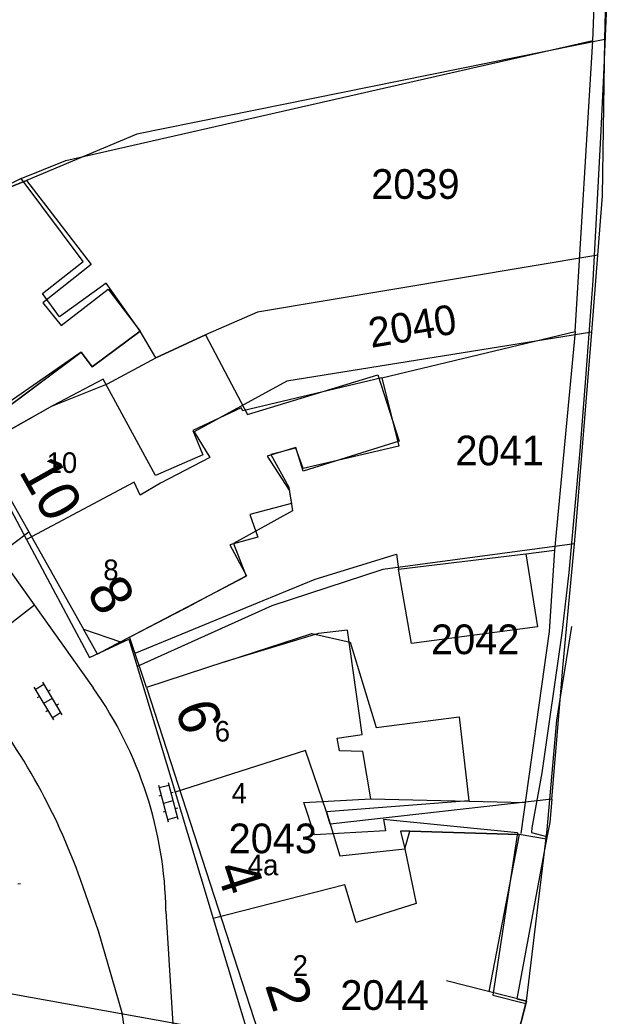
# Model space of a CAD drawing. Extents: x 148816 to 151297, y 399515 to 402500.
# Drawn here: x 150639.1 to 150674.8, y 399934.8 to 399995.1 of the extents above; entities that cross this region are included whole.
import ezdxf

# ---------------------------------------------------------------- set-up
doc = ezdxf.new("R2010")
doc.units = 0
for name, color, linetype in [('B01 Hoofdgebouw  [D] Norm', 7, 'Continuous'), ('B01 Hoofdgebouw  [T] Norm', 7, 'Continuous'), ('B01 hoofgebouw', 7, 'Continuous'), ('B02 Bijgebouw  [T] Norm', 7, 'Continuous'), ('G01 perceelsgrens', 7, 'Continuous'), ('G02 sectiegrens', 7, 'Continuous'), ('S02 Open verharding  Norm', 7, 'Continuous'), ('T04 Haag heg  [D] Gem', 7, 'Continuous'), ('T09 Insteek water  [T] Norm', 7, 'Continuous'), ('V00 Kant verharding algemeen  [T] Norm', 7, 'Continuous'), ('V00 Kant verharding algemeen secundair  [T] Gem', 7, 'Continuous'), ('V06 Kant onverhard  [T] Gem', 7, 'Continuous'), ('Z01 perceelnummer', 7, 'Continuous'), ('Z02 huisnummer', 7, 'Continuous'), ('Z02 Huisnummer  [Tekst] Norm', 7, 'Continuous')]:
    doc.layers.add(name, color=color, linetype=linetype)

msp = doc.modelspace()

# ---------------------------------------------------------------- linework, layer by layer
at = {"layer": 'B01 Hoofdgebouw  [D] Norm'}
for p, q in [((150639.175, 399985.547), (150636.075, 399983.976)), ((150642.93, 399980.516), (150639.175, 399985.547)), ((150640.465, 399978.564), (150642.93, 399980.516)), ((150644.327, 399979.195), (150641.506, 399977.167)), ((150646.38, 399976.28), (150644.327, 399979.195)), ((150641.506, 399977.167), (150640.465, 399978.564)), ((150644.145, 399973.381), (150641.08, 399971.76)), ((150647.316, 399967.539), (150644.145, 399973.381)), ((150661.035, 399973.464), (150652.601, 399971.468)), ((150661.035, 399973.464), (150662.049, 399969.325)), ((150652.5, 399971.646), (150649.578, 399970.278)), ((150652.601, 399971.468), (150652.5, 399971.646)), ((150649.578, 399970.278), (150650.187, 399968.805)), ((150662.049, 399969.325), (150656.257, 399967.961)), ((150650.187, 399968.805), (150647.316, 399967.539)), ((150655.826, 399969.205), (150654.301, 399968.826)), ((150654.301, 399968.826), (150655.392, 399966.845)), ((150656.257, 399967.961), (150655.826, 399969.205)), ((150655.392, 399966.845), (150655.62, 399965.398)), ((150655.62, 399965.398), (150652.037, 399963.422)), ((150652.037, 399963.422), (150652.798, 399961.439)), ((150662.043, 399961.862), (150669.74, 399962.792)), ((150669.74, 399962.792), (150670.448, 399958.375)), ((150662.828, 399957.368), (150662.043, 399961.862)), ((150657.19, 399957.983), (150651.51, 399956.26)), ((150658.942, 399958.184), (150657.19, 399957.983)), ((150659.827, 399951.862), (150658.942, 399958.184)), ((150670.448, 399958.375), (150662.828, 399957.368)), ((150658.328, 399951.636), (150659.827, 399951.862)), ((150658.455, 399950.874), (150658.328, 399951.636)), ((150659.877, 399950.822), (150658.455, 399950.874)), ((150660.358, 399947.952), (150659.877, 399950.822)), ((150656.294, 399947.728), (150660.358, 399947.952)), ((150656.953, 399945.773), (150656.294, 399947.728)), ((150661.119, 399946.708), (150661.245, 399946.022)), ((150669.25, 399945.889), (150661.119, 399946.708)), ((150661.245, 399946.022), (150656.953, 399945.773)), ((150669.25, 399945.889), (150667.741, 399936.064)), ((150667.741, 399936.064), (150669.756, 399935.557))]:
    msp.add_line(p, q, dxfattribs=at)
at = {"layer": 'B01 Hoofdgebouw  [T] Norm'}
for p, q in [((150643.47, 399974.13), (150646.38, 399976.28)), ((150635.68, 399969.73), (150642.82, 399975.01)), ((150642.82, 399975.01), (150643.47, 399974.13)), ((150641.08, 399971.76), (150636.72, 399969.31)), ((150636.72, 399969.31), (150642.95, 399958.24)), ((150645.2, 399957.46), (150652.798, 399961.439)), ((150642.95, 399958.24), (150645.2, 399957.46)), ((150651.51, 399956.26), (150646.76, 399954.71)), ((150646.76, 399954.71), (150653.52, 399933.9)), ((150668.48, 399930.61), (150669.756, 399935.557))]:
    msp.add_line(p, q, dxfattribs=at)
at = {"layer": 'B01 hoofgebouw'}
for points in [[(150632.97, 399981.81), (150635.886, 399983.964), (150639.497, 399985.413), (150643.41, 399980.331), (150640.498, 399978.004), (150641.596, 399976.639), (150644.449, 399978.837), (150646.38, 399976.28)], [(150632.97, 399981.81), (150628.95, 399978.84), (150635.68, 399969.73), (150642.82, 399975.01), (150643.47, 399974.13), (150646.38, 399976.28)], [(150641.08, 399971.76), (150644.412, 399973.093), (150647.341, 399974.68), (150650.345, 399976.06), (150652.884, 399971.24), (150660.788, 399973.653), (150662.076, 399969.631), (150656.253, 399967.812), (150655.81, 399969.247), (150654.088, 399968.721), (150655.404, 399966.648), (150655.549, 399965.849), (150653.028, 399965.179), (150653.513, 399963.802), (150651.826, 399963.353), (150652.835, 399961.459), (150649.63, 399959.78)], [(150641.08, 399971.76), (150636.72, 399969.31), (150642.95, 399958.24), (150645.2, 399957.46), (150649.63, 399959.78)], [(150645.2, 399957.46), (150643.8, 399956.73), (150642.95, 399958.24)], [(150651.51, 399956.26), (150656.776, 399957.978), (150659.109, 399957.442), (150660.692, 399952.271), (150665.71, 399952.921), (150666.304, 399947.834), (150657.67, 399947.177), (150658.487, 399944.494), (150662.412, 399944.935), (150662.727, 399945.988), (150669.351, 399945.8), (150667.499, 399936.28)], [(150651.51, 399956.26), (150646.76, 399954.71), (150653.52, 399933.9), (150664.35, 399931.07), (150664.5, 399931.64), (150668.48, 399930.61), (150669.79, 399935.69), (150664.948, 399936.938)]]:
    msp.add_lwpolyline(points, dxfattribs=at)
at = {"layer": 'B02 Bijgebouw  [T] Norm'}
for p, q in [((150643.8, 399956.73), (150642.95, 399958.24)), ((150645.2, 399957.46), (150643.8, 399956.73))]:
    msp.add_line(p, q, dxfattribs=at)
at = {"layer": 'G01 perceelsgrens'}
for points in [[(150674.539, 399993.954), (150674.672, 400000)], [(150674.539, 399993.954), (150646.187, 399988.232), (150639.497, 399985.413), (150635.886, 399983.964), (150628.571, 399978.56)], [(150674.115, 399980.894), (150674.404, 399984.492), (150674.539, 399993.954)], [(150674.115, 399980.894), (150653.501, 399977.432), (150650.345, 399976.06), (150647.341, 399974.68), (150646.38, 399976.28), (150643.47, 399974.13), (150642.82, 399975.01), (150635.988, 399970.3)], [(150673.742, 399976.233), (150674.115, 399980.894)], [(150673.742, 399976.233), (150655.268, 399973.266), (150649.648, 399970.201), (150650.607, 399968.636), (150647.627, 399967.073), (150646.379, 399966.358), (150646.025, 399967.145), (150639.508, 399963.675)], [(150672.69, 399963.407), (150672.797, 399964.557), (150673.742, 399976.233)], [(150672.69, 399963.407), (150661.084, 399961.853), (150654.363, 399959.64), (150646.201, 399955.973)], [(150671.315, 399947.937), (150672.009, 399956.108), (150672.69, 399963.407)], [(150671.315, 399947.937), (150657.899, 399946.426), (150657.67, 399947.177), (150656.411, 399950.89), (150648.497, 399948.368)], [(150671.315, 399947.937), (150671.194, 399946.52), (150671.006, 399945.506)], [(150671.006, 399945.506), (150669.351, 399945.8), (150662.727, 399945.988), (150662.151, 399945.989), (150662.412, 399944.935), (150663.103, 399941.609), (150659.478, 399940.47), (150658.787, 399942.751), (150650.807, 399940.717)], [(150671.006, 399945.506), (150669.209, 399935.84), (150669.79, 399935.69), (150668.48, 399930.61), (150668.205, 399929.763)], [(150652.977, 399933.528), (150637.48, 399936.33)]]:
    msp.add_lwpolyline(points, dxfattribs=at)
at = {"layer": 'G02 sectiegrens'}
for points in [[(150635.988, 399970.3), (150639.508, 399963.675)], [(150639.508, 399963.675), (150643.311, 399956.515), (150645.7, 399957.631), (150646.201, 399955.973)], [(150646.201, 399955.973), (150648.497, 399948.368)], [(150648.497, 399948.368), (150650.807, 399940.717)], [(150650.807, 399940.717), (150652.977, 399933.528)]]:
    msp.add_lwpolyline(points, dxfattribs=at)
at = {"layer": 'S02 Open verharding  Norm'}
for p, q in [((150640.026, 399954.59), (150640.541, 399954.897)), ((150640.464, 399955.026), (150641.643, 399953.052)), ((150639.949, 399954.718), (150641.128, 399952.744)), ((150640.926, 399954.545), (150640.797, 399954.468)), ((150640.282, 399954.16), (150640.153, 399954.083)), ((150641.054, 399954.039), (150640.538, 399953.731)), ((150641.439, 399953.687), (150641.31, 399953.61)), ((150640.795, 399953.302), (150640.666, 399953.225)), ((150641.051, 399952.873), (150641.566, 399953.18)), ((150648.077, 399948.938), (150648.671, 399946.717)), ((150647.497, 399948.783), (150648.091, 399946.562)), ((150647.536, 399948.639), (150648.116, 399948.794)), ((150648.39, 399948.349), (150648.245, 399948.311)), ((150647.665, 399948.156), (150647.52, 399948.117)), ((150648.374, 399947.827), (150647.794, 399947.673)), ((150647.923, 399947.189), (150647.778, 399947.151)), ((150648.648, 399947.383), (150648.503, 399947.344)), ((150648.052, 399946.706), (150648.632, 399946.861)), ((150639.133, 399942.804), (150638.984, 399942.789))]:
    msp.add_line(p, q, dxfattribs=at)
at = {"layer": 'T04 Haag heg  [D] Gem'}
for p, q in [((150673.808, 399993.882), (150674.037, 399999.72)), ((150641.89, 399986.636), (150673.809, 399993.899)), ((150672.738, 399976.269), (150673.808, 399993.882)), ((150639.175, 399985.547), (150641.89, 399986.636)), ((150661.035, 399973.464), (150672.738, 399976.269)), ((150672.738, 399976.269), (150671.491, 399963.021)), ((150656.992, 399961.275), (150661.918, 399962.771)), ((150661.918, 399962.771), (150662.043, 399961.862)), ((150669.74, 399962.792), (150671.491, 399963.024)), ((150671.491, 399963.021), (150671.159, 399958.097)), ((150653.843, 399959.982), (150656.992, 399961.275)), ((150646.073, 399956.782), (150653.843, 399959.982)), ((150671.159, 399958.097), (150669.456, 399945.864)), ((150646.76, 399954.71), (150645.743, 399957.777)), ((150660.358, 399947.952), (150669.717, 399947.741))]:
    msp.add_line(p, q, dxfattribs=at)
at = {"layer": 'T09 Insteek water  [T] Norm'}
for p, q in [((150674.793, 400000), (150674.459, 399991.803)), ((150674.459, 399991.803), (150674.278, 399988.046)), ((150674.278, 399988.046), (150673.815, 399979.365)), ((150673.815, 399979.365), (150673.38, 399973.704)), ((150673.38, 399973.704), (150673.021, 399969.034)), ((150673.021, 399969.034), (150672.356, 399961.673)), ((150672.356, 399961.673), (150671.921, 399957.992)), ((150671.921, 399957.992), (150670.722, 399949.54)), ((150670.722, 399949.54), (150670.11, 399946.19)), ((150670.11, 399946.19), (150670.084, 399945.911)), ((150670.084, 399945.911), (150671.002, 399945.68))]:
    msp.add_line(p, q, dxfattribs=at)
at = {"layer": 'V00 Kant verharding algemeen  [T] Norm'}
for p, q in [((150671.63, 399952.72), (150672.53, 399958.4)), ((150671.05, 399946.08), (150671.63, 399952.72)), ((150669.79, 399935.69), (150671.05, 399946.08)), ((150643.861, 399939.938), (150642.928, 399942.603)), ((150645.292, 399934.997), (150643.861, 399939.938))]:
    msp.add_line(p, q, dxfattribs=at)
for points in [[(150638.575, 399961.678), (150643.547, 399954.675)], [(150647.947, 399941.148), (150648.473, 399932.688)]]:
    msp.add_lwpolyline(points, dxfattribs=at)
for centre, radius, start, end in [((150606.592, 399930.219), 38.388, 18.81975, 38.98893), ((150623.906, 399940.807), 24.043, 0.81215, 35.22471)]:
    msp.add_arc(centre, radius, start, end, dxfattribs=at)
at = {"layer": 'V00 Kant verharding algemeen secundair  [T] Gem'}
msp.add_line((150645.485, 399933.759), (150645.292, 399934.997), dxfattribs=at)
msp.add_lwpolyline([(150639.981, 399959.695), (150635.213, 399955.986)], dxfattribs=at)
at = {"layer": 'V06 Kant onverhard  [T] Gem'}
msp.add_lwpolyline([(150637.804, 399962.752), (150639.636, 399964.129)], dxfattribs=at)

# ---------------------------------------------------------------- texts
at = {"layer": 'Z01 perceelnummer'}
for s, p in [('2039', (150660.383, 399984.305)), ('2041', (150665.483, 399968.161)), ('2042', (150664.005, 399956.721)), ('2043', (150651.744, 399944.659)), ('2044', (150658.515, 399935.169))]:
    msp.add_text(s, height=1.8, dxfattribs=at).set_placement(p)
msp.add_text('2040', height=1.8, rotation=9.62358, dxfattribs=at).set_placement((150660.379, 399975.274))
at = {"layer": 'Z02 huisnummer'}
for s, rotation, p in [('10', 299.33279, (150639, 399967.806)), ('8', 299.33279, (150643.095, 399960.529)), ('6', 288.00007, (150648.478, 399953.467)), ('4', 288.00007, (150650.948, 399943.748)), ('2', 288.00007, (150653.931, 399936.678))]:
    msp.add_text(s, height=2.5, rotation=rotation, dxfattribs=at).set_placement(p)
at = {"layer": 'Z02 Huisnummer  [Tekst] Norm'}
for s, p in [('10', (150640.712, 399967.7)), ('8', (150644.15, 399961.205)), ('6', (150650.903, 399951.426)), ('4', (150651.921, 399947.675)), ('4a', (150652.899, 399943.324)), ('2', (150655.618, 399937.232))]:
    msp.add_text(s, height=1.25, dxfattribs=at).set_placement(p)

doc.saveas('drawing.dxf')
